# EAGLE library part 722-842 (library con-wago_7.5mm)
Serie 722, Federleiste mit abgewinkelten Einlötstiften / Series 722, Female connector with angled solder pins Polzahl / Pole No.: 12 Rastermaß / Pitch: 7.5 mm Bemessungsspannung / Rated Voltage: 630 V Nennstrom / Nominal Current: 12 A Lötstiftlänge: / Solder Pin Length: 5 mm Farbe / Color: lichtgrau / light gray Stand: 01.01.2012. Die jeweils aktuellen Daten zu diesem Artikel finden Sie in unserem Produktkatalog, den Sie unter www.wago.com einsehen können. As of: 01/01/2012. Please find the newest data for this article in our product catalogue, which can be viewed under www.wago.com.
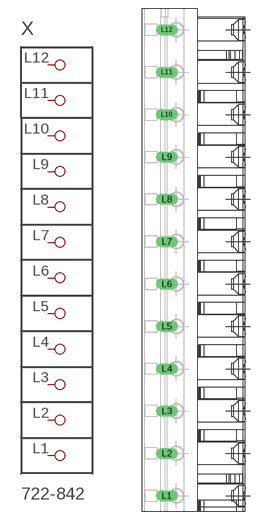
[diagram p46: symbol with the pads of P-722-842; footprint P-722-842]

Designator prefix X

## 722-842  [P-722-842]
L1  P1
L2  P2
L3  P3
L4  P4
L5  P5
L6  P6
L7  P7
L8  P8
L9  P9
L10  P10
L11  P11
L12  P12

## Footprint P-722-842 (pad centres in mm)
drill 1.3 long: L1 -5.186,-41.7; L2 -5.186,-34.2; L3 -5.186,-26.7; L4 -5.186,-19.2; L5 -5.186,-11.7; L6 -5.186,-4.2; L7 -5.186,3.3; L8 -5.186,10.8; L9 -5.186,18.3; L10 -5.186,25.8; L11 -5.186,33.3; L12 -5.186,40.8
